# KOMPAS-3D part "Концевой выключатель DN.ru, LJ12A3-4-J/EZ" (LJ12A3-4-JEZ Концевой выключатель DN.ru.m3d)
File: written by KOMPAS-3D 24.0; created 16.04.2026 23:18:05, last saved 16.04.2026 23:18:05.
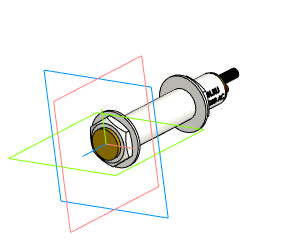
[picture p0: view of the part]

Document properties: Автор: DN.RU; Полное имя файла: D:\PROJECT CAD\DN.RU\...200(ACTUALE). Концевой выключатель DN.ru\Исходники\LJ12A3-4-JEZ\LJ12A3-4-JEZ Концевой выключатель DN.ru.m3d

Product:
- Body: Твердое тело1  | qty 1
    Масса: 0.068116
- Part/product: Концевой выключатель DN.ru  | designation LJ12A3-4-J/EZ
    Масса: 0.05
    Раздел спецификации: Прочие изделия
    Комментарий: D290-00326
    Примечание: D290-00326
    additional columns: Типовые

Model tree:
1. Твердое тело1  (labels: Твердое тело1)

Expressions: LJ12A3-4-J/EZ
